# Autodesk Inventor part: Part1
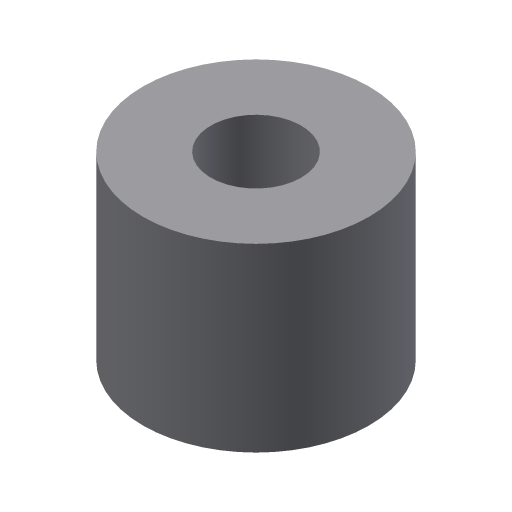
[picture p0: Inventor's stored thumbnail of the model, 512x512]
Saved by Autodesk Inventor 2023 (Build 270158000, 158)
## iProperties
Created: 2002-01
Part Number: Part1
Document SubType Name: Modeling
Designer: ***
Density: 1 g/cm^3
Material: Generic
Appearance: Default
Control State: 0
Master: False
Checked Out: False
Shininess: 77.0
Angle Display Precision: 2
Document Length Units: 11269
Document Angle Units: 11279
Document Time Units: 11290
Document Mass Units: 11283
Document Length Units Precision: 3
Document Angle Units Precision: 2
Density: 0.0
Volumn: 0.0
Area: 0.0
PropertySet Name: Model Information
Author: ***
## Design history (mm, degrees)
sketch "Sketch1"
  geometry: C1 r 25 at (0, 0); C2 r 10 at (0, 0)
  constraints: 2 centre point, 1 coincident
  dimensions: "d0" = 50 diameter of C1; "d1" = 20 diameter of C2
extrude "Extrusion1" new body sketch "Sketch1" distance "d2" = 40; taper "d3" = 0 deg
body "Solid1"
